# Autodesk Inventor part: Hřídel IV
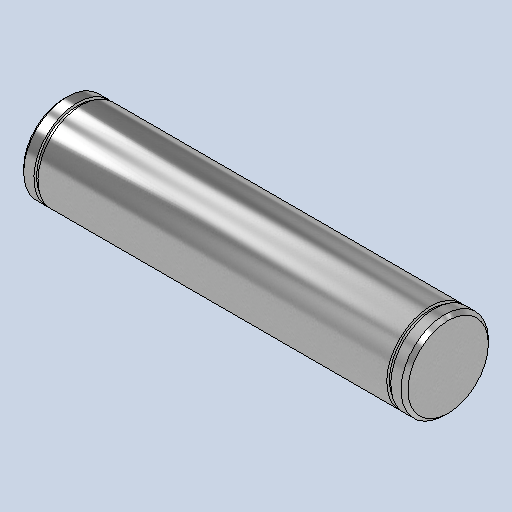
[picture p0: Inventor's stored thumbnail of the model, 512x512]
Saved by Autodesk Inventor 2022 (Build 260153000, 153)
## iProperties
Created: 2025-05
Part Number: Hřídel IV
Material: Všeobecné
Document SubType Name: Modeling
Designer: jbart
Density: 1 g/cm^3
Appearance: Broušená
Mass: 430.306 g
Surface Area: 389.769 cm^2
Volume: 430.306 cm^3
Author: jbart
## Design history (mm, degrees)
sketch "Náčrt1"
  geometry: L1 (0, 0)-(220, 0); L2 (0, 0)-(0, 25); L3 (7.85, 25)-(7.85, 23.5); L4 (7.85, 23.5)-(10.15, 23.5); L5 (10.15, 23.5)-(10.15, 25); L6 (212.15, 23.5)-(212.15, 25); L7 (212.15, 25)-(220, 25); L8 (220, 25)-(220, 0); L9 (115, 25)-(115, 0); L10 (212.15, 23.5)-(209.85, 23.5); L11 (209.85, 23.5)-(209.85, 25); L12 (10.15, 25)-(209.85, 25); L13 (0, 25)-(7.85, 25); 4 further points
  constraints: 26 end point, 5 perpendicular, 4 midpoint, 3 collinear, 3 horizontal, 3 horizontal alignment, 2 parallel, 1 point on line, 1 vertical
  dimensions: "d0" = 220 distance of L1.start L1.end; "d3" = 47 diameter of L4 L1; "d4" = 2.3 distance of L3.end L4.end; "d8" = 115 distance between parallel lines of L2 L9; "d16" = 7.85 distance of L6.end L7.end; "d17" = 50 diameter of L12 L1
revolve "Rotace1" sketch "Náčrt1" stored, may be unused: angle "d11" = 90 deg
chamfer "Zkosení1" distance "d12" = 2; stored, may be unused: second distance "d13" = 2, angle "d14" = 45 deg
node "Těleso1"
